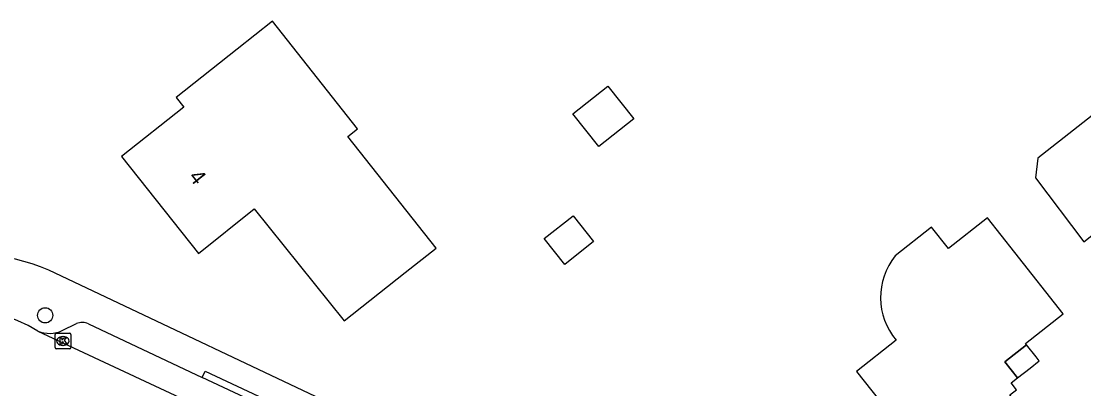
# Model space of a CAD drawing. Extents: x 159628 to 160723, y 388176 to 389416.
# Drawn here: x 159959.9 to 160028.1, y 388636.9 to 388660.5 of the extents above; entities that cross this region are included whole.
import ezdxf

# ---------------------------------------------------------------- set-up
doc = ezdxf.new("R2010")
doc.units = 0
for name, color, linetype in [('IMGEO_Boom', 7, 'Continuous'), ('IMGEO_Kolk', 7, 'Continuous'), ('IMGEO_Pand', 7, 'Continuous'), ('IMGEO_Pand_nummerreeks', 7, 'Continuous'), ('IMGEO_Pand_overbouw', 7, 'Continuous'), ('IMGEO_Rijbaan_lokaal_open', 7, 'Continuous'), ('IMGEO_Voetpad_open', 7, 'Continuous')]:
    doc.layers.add(name, color=color, linetype=linetype)

msp = doc.modelspace()

# ---------------------------------------------------------------- linework, layer by layer
at = {"layer": 'IMGEO_Boom'}
msp.add_circle((159961.483, 388641.658), 0.489, dxfattribs=at)
at = {"layer": 'IMGEO_Kolk'}
for p, q in [((159962.119, 388639.586), (159962.119, 388640.438)), ((159962.194, 388640.512), (159963.046, 388640.512)), ((159962.607, 388640.292), (159962.632, 388640.292)), ((159963.12, 388640.438), (159963.12, 388639.586)), ((159963.046, 388639.512), (159962.194, 388639.512)), ((159962.63, 388639.732), (159962.605, 388639.732))]:
    msp.add_line(p, q, dxfattribs=at)
for points in [[(159962.119, 388639.586), (159962.119, 388640.438)], [(159962.194, 388640.512), (159963.046, 388640.512)], [(159962.44, 388640.212), (159962.563, 388640.212), (159962.563, 388640.061), (159962.693, 388640.212), (159962.857, 388640.212), (159962.711, 388640.061), (159962.864, 388639.812), (159962.712, 388639.812), (159962.627, 388639.976), (159962.563, 388639.909), (159962.563, 388639.812), (159962.44, 388639.812), (159962.44, 388640.212)], [(159963.12, 388640.438), (159963.12, 388639.586)], [(159963.046, 388639.512), (159962.194, 388639.512)]]:
    msp.add_lwpolyline(points, dxfattribs=at)
for centre, start, end in [((159962.196, 388640.436), 91.55205, 178.44795), ((159962.196, 388640.436), 91.55205, 178.44795), ((159963.044, 388640.436), 1.55205, 88.44795), ((159963.044, 388640.436), 1.55205, 88.44795), ((159962.196, 388639.588), 181.55205, 268.44795), ((159962.196, 388639.588), 181.55205, 268.44795), ((159963.044, 388639.588), 271.55205, 358.44795), ((159963.044, 388639.588), 271.55205, 358.44795)]:
    msp.add_arc(centre, 0.0765, start, end, dxfattribs=at)
for centre, major_axis, ratio, start_param, end_param in [((159962.606, 388640.012), (-0.387, 0.002), 0.722429, 4.712389, 7.853982), ((159962.631, 388640.012), (-0.39, 0.002), 0.717154, 1.570796, 4.712389)]:
    msp.add_ellipse(centre, major_axis=major_axis, ratio=ratio, start_param=start_param, end_param=end_param, dxfattribs=at)
at = {"layer": 'IMGEO_Pand'}
for points in [[(159984.577, 388644.407), (159986.558, 388645.973), (159980.897, 388653.134), (159981.523, 388653.629), (159976.066, 388660.532), (159973.805, 388658.745), (159969.882, 388655.644), (159970.377, 388655.018), (159966.37, 388651.85), (159971.32, 388645.631), (159974.884, 388648.501), (159980.655, 388641.305), (159984.577, 388644.407)], [(160038.099, 388645.273), (160039.388, 388646.307), (160037.965, 388648.112), (160038.404, 388648.457), (160038.066, 388648.889), (160038.468, 388649.206), (160037.662, 388650.239), (160039.052, 388651.36), (160038.983, 388651.446), (160041.386, 388653.37), (160038.257, 388657.27), (160036.509, 388659.448), (160034.071, 388657.528), (160035.636, 388655.54), (160033.175, 388653.603), (160031.57, 388655.651), (160030.307, 388655.804), (160025.136, 388651.75), (160024.983, 388650.487), (160028.086, 388646.375), (160029.737, 388647.674), (160031.017, 388646.047), (160034.11, 388642.119), (160035.421, 388643.16)], [(159997.576, 388656.359), (159999.233, 388654.262), (159996.984, 388652.484), (159995.326, 388654.581), (159997.576, 388656.359)], [(159995.348, 388648.05), (159996.658, 388646.392), (159994.799, 388644.922), (159993.488, 388646.58), (159995.348, 388648.05)], [(160023.483, 388633.684), (160024.769, 388634.742), (160023.342, 388636.546), (160023.771, 388636.886), (160023.432, 388637.316), (160023.839, 388637.638), (160023.027, 388638.666), (160024.422, 388639.771), (160024.352, 388639.86), (160026.758, 388641.763), (160023.662, 388645.69), (160021.912, 388647.91), (160019.414, 388645.941), (160018.333, 388647.313), (160016.003, 388645.476)], [(160016.053, 388640.059), (160013.522, 388638.063), (160016.378, 388634.44), (160019.474, 388630.513), (160020.78, 388631.548)]]:
    msp.add_lwpolyline(points, dxfattribs=at)
msp.add_arc((160019.303, 388642.798), 4.25, 140.9335, 220.12417, dxfattribs=at)
at = {"layer": 'IMGEO_Pand_overbouw'}
msp.add_lwpolyline([(160023.839, 388637.638), (160024.648, 388638.278), (160025.236, 388638.743), (160025.037, 388638.994), (160024.422, 388639.771), (160023.027, 388638.666)], close=True, dxfattribs=at)
at = {"layer": 'IMGEO_Rijbaan_lokaal_open'}
msp.add_lwpolyline([(159961.021, 388640.652), (159980.906, 388631.34)], dxfattribs=at)
msp.add_arc((159955.255, 388631.046), 11.204, 59.02371, 117.26616, dxfattribs=at)
at = {"layer": 'IMGEO_Voetpad_open'}
for points in [[(159986.01, 388633.035), (159982.465, 388634.72), (159961.709, 388644.549)], [(159962.582, 388640.687), (159963.493, 388641.127)], [(159964.258, 388641.113), (159971.546, 388637.677)], [(159971.546, 388637.677), (159971.739, 388638.078), (159975.157, 388636.481), (159974.977, 388636.06)], [(159974.977, 388636.06), (159971.546, 388637.677)]]:
    msp.add_lwpolyline(points, dxfattribs=at)
for centre, radius, start, end in [((159956.977, 388633.896), 11.656, 66.05054, 110.10889), ((159961.763, 388642.371), 1.872, 246.64012, 295.92877), ((159963.859, 388640.246), 0.955, 65.32509, 112.57805)]:
    msp.add_arc(centre, radius, start, end, dxfattribs=at)

# ---------------------------------------------------------------- texts
at = {"layer": 'IMGEO_Pand_nummerreeks'}
msp.add_text('4', height=1, rotation=308.51796, dxfattribs=at).set_placement((159970.645, 388650.526))

doc.saveas('drawing.dxf')
